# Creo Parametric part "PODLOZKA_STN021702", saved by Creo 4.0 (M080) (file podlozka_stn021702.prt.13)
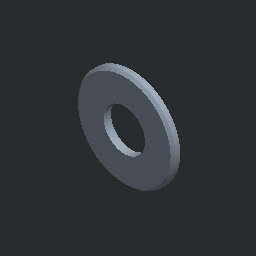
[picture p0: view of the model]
Units: Custom; MM, KILOGRAM, SECS
Materials in the file: OCEL, OCEL_N

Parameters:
  PTC_MATERIAL_NAME = "OCEL"
  NAZOV = "PODLOZKA_STN021702"
  NORMA = "STN 02 1702"

Other parameters: HMOTNOST, HUSTOTA

Created from: C021702.PRT

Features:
  1. chamfer

Layers: 1, 2, 3, 4, 5, 6, 7, 8, 9, 10, 11, 12, 13, 14, 15, 16, 17, 18, 19, 20, 21, 22, 23, 24, 25, 26, 27, 28, 29, 30, 31, 32

Family table entries: GENERIC, PODLOZKA_1_7, PODLOZKA_STN021702, value(d_val), value(i_val), PODLOZKA_2_2, PODLOZKA_STN021702, PODLOZKA_2_7, PODLOZKA_STN021702, PODLOZKA_3_2, PODLOZKA_STN021702, PODLOZKA_3_7, PODLOZKA_STN021702, PODLOZKA_4_3, PODLOZKA_STN021702, 2/", PODLOZKA_5_3, PODLOZKA_STN021702, 2/$, PODLOZKA_6_4, PODLOZKA_STN021702, 2/), PODLOZKA_7_4, PODLOZKA_STN021702, 2/,, PODLOZKA_8_4, PODLOZKA_STN021702, 2/1, PODLOZKA_B8_4, PODLOZKA_STN021702, 2/1, PODLOZKA_10_5, PODLOZKA_STN021702, !/%, 2/5, PODLOZKA_B10_5, PODLOZKA_STN021702, !/%, 2/5, PODLOZKA_13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

Surfaces: 2 plane, 2 cylinder, 2 cone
